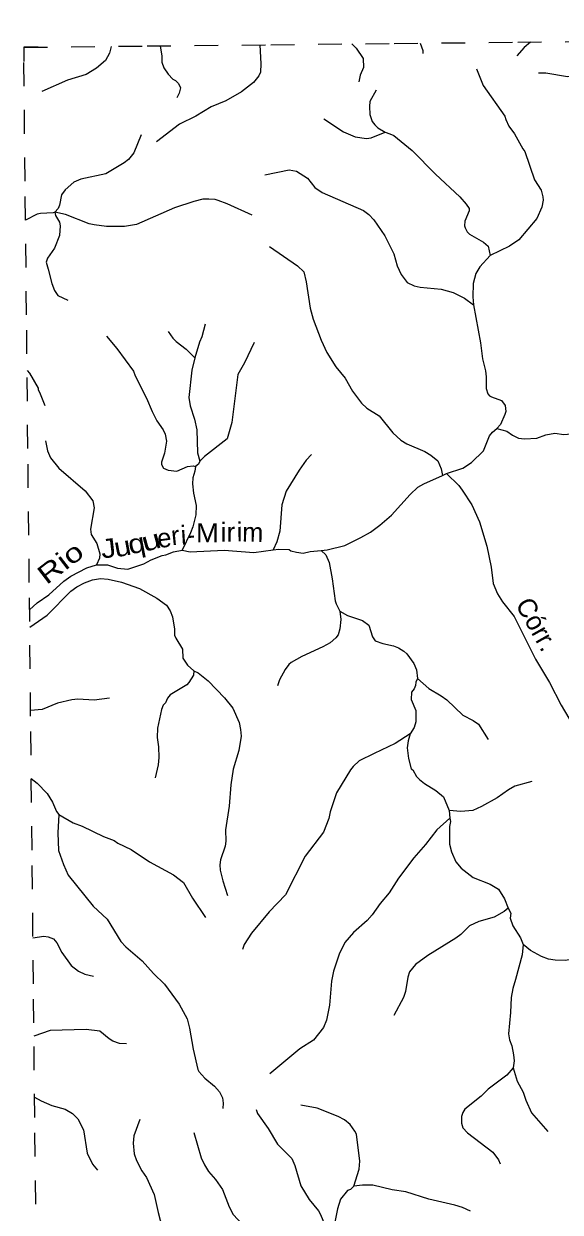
# Model space of a CAD drawing. Extents: x 346.5 to 372.4, y 7400.3 to 7428.2.
# Drawn here: x 346.55 to 348.82, y 7423.08 to 7428.1 of the extents above; entities that cross this region are included whole.
import ezdxf
from ezdxf.enums import TextEntityAlignment as Align

# ---------------------------------------------------------------- set-up
doc = ezdxf.new("R2010")
doc.units = 0
doc.header["$LTSCALE"] = 0.032
doc.linetypes.add('SHORT_DASHED', pattern=[2.7, 1.5, -1.2])
for name, color, linetype, lineweight in [('53', 7, 'SHORT_DASHED', 13), ('63', 7, 'Continuous', 25), ('7', 7, 'Continuous', 25)]:
    doc.layers.add(name, color=color, linetype=linetype, lineweight=lineweight)
doc.layers.add('61', color=7, linetype='Continuous')

msp = doc.modelspace()

# ---------------------------------------------------------------- linework, layer by layer
at = {"layer": '53'}
for points in [[(346.5495, 7428.0029), (347.0715, 7428.0083), (347.5936, 7428.0137), (348.1156, 7428.019), (348.6376, 7428.0243), (349.1596, 7428.0297), (349.6816, 7428.035), (350.2036, 7428.0402), (350.7257, 7428.0455), (351.2477, 7428.0507), (351.7697, 7428.0559), (352.2917, 7428.0611), (352.8137, 7428.0663), (353.3357, 7428.0715), (353.8577, 7428.0766), (354.3798, 7428.0818), (354.9018, 7428.0869), (355.4238, 7428.092), (355.9458, 7428.0971), (356.4678, 7428.1021)], [(346.6314, 7420.0936), (346.6255, 7420.6585), (346.6197, 7421.2235), (346.6138, 7421.7885), (346.608, 7422.3534), (346.6021, 7422.9184), (346.5963, 7423.4833), (346.5904, 7424.0483), (346.5846, 7424.6132), (346.5787, 7425.1782), (346.5729, 7425.7431), (346.567, 7426.3081), (346.5612, 7426.873), (346.5553, 7427.438), (346.5495, 7428.0029)]]:
    msp.add_lwpolyline(points, dxfattribs=at)
at = {"layer": '63'}
msp.add_lwpolyline([(346.6111, 7428.0029), (346.5495, 7428.0029), (346.5495, 7427.9422)], dxfattribs=at)
at = {"layer": '7'}
for points in [[(346.919, 7428.0067), (346.9124, 7427.9785), (346.8956, 7427.9466), (346.8574, 7427.9147), (346.8136, 7427.8885), (346.7347, 7427.8645), (346.6255, 7427.8167)], [(347.548, 7428.0132), (347.5523, 7427.9323), (347.5507, 7427.898), (347.5435, 7427.8829), (347.5204, 7427.8542), (347.4694, 7427.8151), (347.4041, 7427.7761), (347.3411, 7427.7514), (347.2766, 7427.7115), (347.208, 7427.6781), (347.11, 7427.6032)], [(347.1258, 7428.0089), (347.1331, 7427.9658), (347.1331, 7427.9403), (347.1419, 7427.9164), (347.1602, 7427.8893), (347.1801, 7427.8685), (347.1913, 7427.863), (347.2041, 7427.8502), (347.212, 7427.8319), (347.2064, 7427.8096), (347.1961, 7427.7896)], [(347.9368, 7428.0172), (347.9548, 7427.9992), (347.9842, 7427.9554), (347.9858, 7427.9172), (347.9715, 7427.8853), (347.9659, 7427.8566)], [(348.2254, 7428.0201), (348.2361, 7427.9889), (348.2361, 7427.9761)], [(348.6916, 7428.0248), (348.6648, 7428.0024), (348.6338, 7427.9666)], [(348.4632, 7427.9124), (348.4919, 7427.8415), (348.5836, 7427.7123), (348.5867, 7427.698), (348.6003, 7427.6693), (348.6234, 7427.6374), (348.6593, 7427.5737), (348.668, 7427.5633), (348.7087, 7427.443), (348.7358, 7427.3999), (348.7437, 7427.3713), (348.7445, 7427.3569), (348.7398, 7427.3282), (348.7182, 7427.2804), (348.6425, 7427.1903), (348.6027, 7427.1624), (348.5214, 7427.1235)], [(349.2997, 7427.832), (349.2642, 7427.8446), (349.2355, 7427.859), (349.1622, 7427.9044), (349.1303, 7427.9179), (349.1143, 7427.9211), (349.0681, 7427.9243), (349.0251, 7427.9203), (348.9964, 7427.9108), (348.9534, 7427.8901), (348.88, 7427.8789), (348.8482, 7427.8781), (348.7557, 7427.8932), (348.7246, 7427.8941)], [(348.0393, 7427.8215), (348.0129, 7427.7745), (348.0106, 7427.7522), (348.0129, 7427.7187), (348.0225, 7427.69), (348.0337, 7427.6757), (348.0464, 7427.6629), (348.0773, 7427.645)], [(347.8177, 7427.7004), (347.9006, 7427.6462), (347.9508, 7427.6247), (347.9986, 7427.6183), (348.0177, 7427.6207), (348.0773, 7427.645)], [(348.0773, 7427.645), (348.0974, 7427.638), (348.1139, 7427.6308), (348.1915, 7427.5665), (348.2895, 7427.4677), (348.3923, 7427.3712), (348.4194, 7427.341), (348.4321, 7427.3226), (348.4321, 7427.3123), (348.4138, 7427.2692), (348.4122, 7427.2485), (348.4146, 7427.2406), (348.4234, 7427.2238), (348.4337, 7427.2142), (348.4927, 7427.1792), (348.5118, 7427.1632), (348.5214, 7427.1235)], [(347.0463, 7427.6334), (347.0144, 7427.5577), (346.9929, 7427.529), (346.9745, 7427.5147), (346.8964, 7427.4685), (346.7904, 7427.4461), (346.7617, 7427.4334), (346.7251, 7427.4007), (346.7091, 7427.3792), (346.7012, 7427.3362), (346.6948, 7427.3218), (346.6816, 7427.3068)], [(347.5691, 7427.4645), (347.6719, 7427.486), (347.7029, 7427.4796), (347.7484, 7427.4501), (347.7802, 7427.4103), (347.8105, 7427.3896), (347.9859, 7427.3131), (348.0082, 7427.2963), (348.0297, 7427.2748), (348.0751, 7427.2071), (348.1134, 7427.1306), (348.1285, 7427.0796), (348.1444, 7427.0429), (348.17, 7427.0102), (348.1994, 7426.9959), (348.2249, 7426.9895), (348.3142, 7426.9815), (348.3652, 7426.968), (348.413, 7426.9433), (348.4507, 7426.9158)], [(347.5149, 7427.2939), (347.4089, 7427.3418), (347.3706, 7427.3561), (347.3579, 7427.3601), (347.3324, 7427.3617), (347.3069, 7427.3609), (347.2686, 7427.3521), (347.1873, 7427.3242), (347.0263, 7427.2549), (346.9753, 7427.2461), (346.8988, 7427.2461), (346.8478, 7427.2525), (346.8255, 7427.2573), (346.7259, 7427.2971), (346.6816, 7427.3068)], [(346.6816, 7427.3068), (346.6741, 7427.3033), (346.6199, 7427.3011), (346.6056, 7427.2979), (346.557, 7427.2731)], [(346.6816, 7427.3068), (346.6836, 7427.293), (346.7004, 7427.2645), (346.7028, 7427.2485), (346.7012, 7427.2079), (346.6789, 7427.1545), (346.6506, 7427.1117), (346.6445, 7427.0948), (346.6526, 7427.0652), (346.6677, 7427.0047), (346.6797, 7426.976), (346.6932, 7426.9552), (346.7355, 7426.9345)], [(347.5882, 7427.1617), (347.7061, 7427.0804), (347.7332, 7427.0549), (347.7436, 7427.0126), (347.7595, 7426.9011), (347.7731, 7426.8548), (347.8065, 7426.7656), (347.8312, 7426.7146), (347.8687, 7426.654), (347.9077, 7426.6062), (347.9388, 7426.5504), (347.9771, 7426.4994), (347.9994, 7426.4787), (348.052, 7426.4468), (348.1102, 7426.3743), (348.1436, 7426.3432), (348.1692, 7426.328), (348.2441, 7426.2962), (348.2696, 7426.281), (348.2998, 7426.2563), (348.3062, 7426.2396), (348.3134, 7426.2221), (348.3193, 7426.1943)], [(348.5214, 7427.1235), (348.4768, 7427.0764), (348.4608, 7427.0477), (348.4497, 7427.0047), (348.4473, 7426.9497), (348.4507, 7426.9158)], [(348.4507, 7426.9158), (348.4807, 7426.7544), (348.4879, 7426.6875), (348.5007, 7426.6365), (348.5039, 7426.611), (348.5039, 7426.5616), (348.511, 7426.54), (348.5182, 7426.5313), (348.5262, 7426.5273), (348.5692, 7426.5113), (348.5844, 7426.4898), (348.5867, 7426.4643), (348.5836, 7426.4516), (348.5641, 7426.4093), (348.5493, 7426.3934)], [(347.3164, 7426.8333), (347.3021, 7426.7799), (347.2925, 7426.7576), (347.2729, 7426.6918)], [(346.8996, 7426.7823), (346.9426, 7426.7305), (347.0136, 7426.6349), (347.0199, 7426.6157), (347.0678, 7426.5217), (347.0925, 7426.4643), (347.1124, 7426.4261), (347.1387, 7426.3878), (347.1467, 7426.3687), (347.1522, 7426.34), (347.1443, 7426.289), (347.1323, 7426.2507), (347.1323, 7426.2404), (347.1395, 7426.226), (347.1594, 7426.2165), (347.1961, 7426.2125), (347.2415, 7426.2332), (347.2656, 7426.235), (347.275, 7426.2326)], [(347.1594, 7426.803), (347.1801, 7426.7743), (347.1937, 7426.7608), (347.2367, 7426.7281), (347.2729, 7426.6918)], [(347.5236, 7426.7568), (347.4822, 7426.6699), (347.4543, 7426.6205), (347.4296, 7426.4181), (347.4089, 7426.3488), (347.3132, 7426.2754), (347.2933, 7426.2551)], [(347.2729, 7426.6918), (347.2606, 7426.6397), (347.2479, 7426.5233), (347.2527, 7426.4882), (347.271, 7426.4325), (347.2805, 7426.3878), (347.2845, 7426.2906), (347.2933, 7426.2551)], [(346.5636, 7426.6378), (346.5744, 7426.6269), (346.6103, 7426.5639), (346.6103, 7426.5576), (346.6191, 7426.5401), (346.6385, 7426.49)], [(348.3369, 7426.2025), (348.4051, 7426.2252), (348.4417, 7426.2499), (348.4927, 7426.2994), (348.5182, 7426.3623), (348.5302, 7426.3775), (348.5493, 7426.3934)], [(348.5493, 7426.3934), (348.5915, 7426.3822), (348.6154, 7426.3655), (348.641, 7426.3527), (348.6665, 7426.3496), (348.7175, 7426.3527), (348.7557, 7426.3663), (348.794, 7426.3735), (348.8322, 7426.3671), (348.8936, 7426.3735), (348.9119, 7426.3615), (348.9191, 7426.3424), (348.9271, 7426.3376), (348.9461, 7426.3404), (348.9543, 7426.3487)], [(346.6412, 7426.3404), (346.6494, 7426.2986), (346.6629, 7426.2699), (346.6972, 7426.2252), (346.8088, 7426.1296), (346.8422, 7426.0874), (346.847, 7426.0579), (346.8311, 7425.9686), (346.8343, 7425.9455), (346.8582, 7425.9081), (346.8706, 7425.8639), (346.8694, 7425.8451), (346.8577, 7425.818)], [(347.7659, 7426.2834), (347.7436, 7426.2587), (347.7133, 7426.2173), (347.6583, 7426.1288), (347.6408, 7426.0706), (347.632, 7425.9591), (347.6192, 7425.9144), (347.6039, 7425.8811)], [(347.275, 7426.2326), (347.2727, 7426.213), (347.2638, 7426.1854), (347.2622, 7426.1599), (347.267, 7426.12), (347.2782, 7426.0675), (347.2766, 7426.0292), (347.2638, 7425.9782), (347.2542, 7425.9527), (347.2195, 7425.8787)], [(347.2933, 7426.2551), (347.2878, 7426.2427), (347.275, 7426.2326)], [(347.8065, 7425.8778), (347.8324, 7425.8813), (347.9062, 7425.8993), (347.9747, 7425.9327), (348.0153, 7425.9559), (348.0544, 7425.9845), (348.1038, 7426.0268), (348.1835, 7426.1145), (348.2154, 7426.1447), (348.2409, 7426.1591), (348.3193, 7426.1943), (348.3369, 7426.2025)], [(348.3369, 7426.2025), (348.3883, 7426.1527), (348.4026, 7426.132), (348.4433, 7426.0706), (348.476, 7425.9989), (348.5063, 7425.8969), (348.5246, 7425.8076), (348.5333, 7425.7391), (348.5525, 7425.6945), (348.5724, 7425.661), (348.6226, 7425.5996), (348.7127, 7425.4187), (348.7716, 7425.3207), (348.821, 7425.2243), (348.8529, 7425.1701), (348.8816, 7425.131), (348.9478, 7425.0561), (348.9924, 7425.0059), (349.0314, 7424.9477)], [(346.8577, 7425.818), (346.9036, 7425.818), (346.9451, 7425.8036), (346.9897, 7425.7997), (347.0566, 7425.822), (347.0877, 7425.8387), (347.1347, 7425.8562), (347.1507, 7425.8594), (347.1825, 7425.8722), (347.2195, 7425.8787)], [(347.2195, 7425.8787), (347.2536, 7425.8716), (347.3961, 7425.8794), (347.522, 7425.8698), (347.6039, 7425.8811)], [(347.6039, 7425.8811), (347.6274, 7425.8835), (347.6715, 7425.8817), (347.6782, 7425.877), (347.7021, 7425.8706), (347.7308, 7425.8666), (347.7595, 7425.873), (347.8065, 7425.8778)], [(347.8065, 7425.8778), (347.8258, 7425.8597), (347.8403, 7425.8273), (347.8536, 7425.7582), (347.8663, 7425.6658), (347.8695, 7425.653), (347.8849, 7425.6218)], [(346.5741, 7425.628), (346.6056, 7425.657), (346.6549, 7425.6913), (346.7187, 7425.7487), (346.7482, 7425.7702), (346.8159, 7425.8052), (346.8577, 7425.818)], [(346.5748, 7425.5541), (346.6478, 7425.6044), (346.7482, 7425.7056), (346.7745, 7425.7247), (346.8064, 7425.7415), (346.8399, 7425.7542), (346.8733, 7425.7598), (346.9068, 7425.7566), (346.9626, 7425.7447), (347.0391, 7425.7168), (347.1124, 7425.6761), (347.153, 7425.6467), (347.1682, 7425.6228), (347.1777, 7425.5973), (347.1865, 7425.5462), (347.1873, 7425.5207), (347.1921, 7425.508), (347.2208, 7425.461), (347.2224, 7425.4235), (347.2423, 7425.3932), (347.2682, 7425.3699)], [(347.8849, 7425.6218), (347.8902, 7425.5861), (347.8862, 7425.5478), (347.8783, 7425.5223), (347.8687, 7425.5088), (347.844, 7425.4881), (347.8137, 7425.4705), (347.7245, 7425.4307), (347.6798, 7425.4052), (347.6703, 7425.3972), (347.6551, 7425.3757), (347.6312, 7425.3311), (347.6217, 7425.3064)], [(347.8849, 7425.6218), (347.9173, 7425.6028), (347.9811, 7425.5821), (348.0074, 7425.563), (348.0241, 7425.5128), (348.0353, 7425.4968), (348.0671, 7425.4849), (348.1118, 7425.4753), (348.1341, 7425.4673), (348.1556, 7425.4522), (348.1683, 7425.441), (348.1986, 7425.4012), (348.209, 7425.3741), (348.2144, 7425.3378)], [(347.2682, 7425.3699), (347.2667, 7425.3511), (347.2479, 7425.3207), (347.2383, 7425.3111), (347.1682, 7425.2681), (347.157, 7425.2546), (347.1483, 7425.2346), (347.1387, 7425.2243), (347.1315, 7425.2067), (347.1148, 7425.1271), (347.114, 7425.0888), (347.1196, 7425.049), (347.1204, 7425.0043), (347.1172, 7424.9724), (347.1044, 7424.9175)], [(347.2682, 7425.3699), (347.2861, 7425.3609), (347.3284, 7425.3271), (347.3977, 7425.2554), (347.4336, 7425.2115), (347.4599, 7425.151), (347.4662, 7425.1223), (347.4678, 7425.0936), (347.4583, 7425.033), (347.4344, 7424.9549), (347.4248, 7424.888), (347.4176, 7424.7987), (347.4025, 7424.6983), (347.4041, 7424.6505), (347.4005, 7424.6288), (347.381, 7424.5724), (347.3786, 7424.5501), (347.3802, 7424.5278), (347.3913, 7424.4831), (347.4105, 7424.4218)], [(348.2144, 7425.3378), (348.2062, 7425.3219), (348.205, 7425.3072), (348.1994, 7425.2944), (348.1883, 7425.2801), (348.1867, 7425.249), (348.2066, 7425.2028), (348.2066, 7425.1542), (348.1994, 7425.131), (348.1821, 7425.1043)], [(348.2144, 7425.3378), (348.2612, 7425.2952), (348.3142, 7425.2649), (348.3381, 7425.2474), (348.4058, 7425.1828), (348.4497, 7425.1605), (348.472, 7425.1446), (348.5118, 7425.08)], [(346.9124, 7425.2546), (346.8478, 7425.2458), (346.7777, 7425.2498), (346.7522, 7425.2474), (346.6916, 7425.233), (346.6279, 7425.2059), (346.5785, 7425.2021)], [(348.1821, 7425.1043), (348.1197, 7425.0633), (348.0305, 7425.021), (347.9667, 7424.99), (347.9412, 7424.9661), (347.9309, 7424.9517), (347.8711, 7424.8545), (347.8448, 7424.7748), (347.8384, 7424.7461), (347.8169, 7424.6887), (347.7388, 7424.5867), (347.6559, 7424.4241), (347.5866, 7424.3516), (347.5125, 7424.2616), (347.4814, 7424.2138), (347.4742, 7424.1938)], [(348.1821, 7425.1043), (348.1739, 7425.0745), (348.1707, 7425.0442), (348.1755, 7424.9995), (348.1875, 7424.9565), (348.1939, 7424.9517), (348.2098, 7424.923), (348.2225, 7424.9103), (348.2433, 7424.8935), (348.2919, 7424.864), (348.3238, 7424.8377), (348.348, 7424.7798), (348.3501, 7424.7481)], [(346.5815, 7424.9158), (346.6063, 7424.8959), (346.6486, 7424.8513), (346.6717, 7424.8147), (346.6878, 7424.7755), (346.6974, 7424.7631)], [(348.6975, 7424.9023), (348.625, 7424.8824), (348.5987, 7424.868), (348.5501, 7424.8338), (348.4847, 7424.7971), (348.4481, 7424.7804), (348.3971, 7424.7764), (348.348, 7424.7798)], [(346.6974, 7424.7631), (346.6932, 7424.6855), (346.6964, 7424.6106), (346.7171, 7424.5517), (346.737, 7424.507), (346.843, 7424.3755), (346.9028, 7424.3205), (346.9594, 7424.2273), (346.9817, 7424.2042), (347.0502, 7424.1452), (347.098, 7424.0918), (347.1443, 7424.0464), (347.2064, 7423.9619), (347.2407, 7423.8998), (347.2503, 7423.8615), (347.2654, 7423.7722), (347.2853, 7423.6862), (347.2901, 7423.6774), (347.3156, 7423.6503), (347.3563, 7423.616), (347.377, 7423.5921), (347.3897, 7423.5666), (347.3929, 7423.5443), (347.3905, 7423.5212)], [(346.6974, 7424.7631), (346.7586, 7424.7278), (346.7968, 7424.7134), (346.8861, 7424.6704), (346.9323, 7424.6528), (346.9474, 7424.6417), (347.004, 7424.6154), (347.0805, 7424.5628), (347.1825, 7424.5086), (347.2248, 7424.4759), (347.2622, 7424.4098), (347.3172, 7424.3277)], [(348.3501, 7424.7481), (348.2951, 7424.6991), (348.248, 7424.6361), (348.1978, 7424.5803), (348.1341, 7424.4943), (348.0934, 7424.4329), (348.056, 7424.3875), (348.0217, 7424.3389), (348.001, 7424.315), (347.9436, 7424.2647), (347.9062, 7424.2225), (347.883, 7424.1739), (347.8583, 7424.1022), (347.8496, 7424.0591), (347.8416, 7423.9587), (347.8296, 7423.895), (347.8169, 7423.8631), (347.7739, 7423.8097), (347.7165, 7423.7738), (347.5898, 7423.6678)], [(348.3501, 7424.7481), (348.3528, 7424.7336), (348.3491, 7424.7127), (348.3493, 7424.6377), (348.3572, 7424.6059), (348.3763, 7424.5628), (348.3987, 7424.5365), (348.4497, 7424.4967), (348.5214, 7424.4696), (348.5557, 7424.4472), (348.5812, 7424.4066), (348.597, 7424.367)], [(348.597, 7424.367), (348.5804, 7424.3532), (348.5373, 7424.3301), (348.4736, 7424.3118), (348.4337, 7424.2934), (348.3971, 7424.2568), (348.3764, 7424.2416), (348.2568, 7424.1683), (348.2058, 7424.1293), (348.1795, 7424.099), (348.1723, 7424.0767), (348.1628, 7424.0161), (348.1548, 7423.9906), (348.1142, 7423.9149)], [(348.597, 7424.367), (348.608, 7424.3463), (348.6059, 7424.3261), (348.617, 7424.2934), (348.6489, 7424.2424), (348.6611, 7424.2141)], [(346.5884, 7424.2419), (346.6342, 7424.2488), (346.6534, 7424.2464), (346.6757, 7424.2385), (346.6892, 7424.2217), (346.7099, 7424.1811), (346.7506, 7424.1261), (346.7816, 7424.1014), (346.808, 7424.0894), (346.8438, 7424.0799)], [(349.1853, 7424.2448), (349.1287, 7424.2329), (349.0219, 7424.2217), (349.0075, 7424.2177), (348.9796, 7424.2074), (348.9263, 7424.1747), (348.8976, 7424.1611), (348.8705, 7424.1516), (348.8386, 7424.146), (348.7956, 7424.1476), (348.7669, 7424.1524), (348.7382, 7424.1635), (348.692, 7424.1882), (348.6611, 7424.2141)], [(348.6611, 7424.2141), (348.6566, 7424.1711), (348.6282, 7424.0671), (348.6162, 7424.0289), (348.6099, 7423.9906), (348.6075, 7423.9269), (348.5987, 7423.8376), (348.6027, 7423.8121), (348.613, 7423.7866), (348.6202, 7423.7483), (348.6218, 7423.7228), (348.6181, 7423.693)], [(346.9841, 7423.7946), (346.9546, 7423.7961), (346.9259, 7423.8065), (346.91, 7423.8161), (346.8717, 7423.8487), (346.8128, 7423.8551), (346.6613, 7423.8511), (346.5927, 7423.8266)], [(348.6181, 7423.693), (348.5907, 7423.6631), (348.5126, 7423.6033), (348.4831, 7423.5738), (348.4138, 7423.5188), (348.405, 7423.5053), (348.4003, 7423.4877), (348.4003, 7423.4598), (348.4058, 7423.4399), (348.4258, 7423.4184), (348.5326, 7423.3371), (348.5565, 7423.3052), (348.5636, 7423.2885)], [(348.6181, 7423.693), (348.6346, 7423.6376), (348.6609, 7423.5905), (348.6712, 7423.5571), (348.6959, 7423.5029), (348.7645, 7423.424)], [(346.5954, 7423.569), (346.6231, 7423.5547), (346.6677, 7423.5339), (346.7243, 7423.5196), (346.7562, 7423.5005), (346.7777, 7423.4782), (346.8016, 7423.4312), (346.8175, 7423.3331), (346.8406, 7423.2869), (346.8614, 7423.2614)], [(347.9444, 7423.1931), (347.9667, 7423.2654), (347.9699, 7423.2989), (347.9564, 7423.4136), (347.9492, 7423.4264), (347.9285, 7423.4535), (347.9046, 7423.4734), (347.8791, 7423.4885), (347.7898, 7423.5236), (347.7205, 7423.5364)], [(347.0399, 7423.475), (347.0152, 7423.4057), (347.012, 7423.3754), (347.0168, 7423.3307), (347.0263, 7423.302), (347.0486, 7423.259), (347.0678, 7423.2303), (347.1004, 7423.1586), (347.1172, 7423.0821), (347.1267, 7423.0502), (347.1411, 7423.0183), (347.1602, 7422.9865), (347.2016, 7422.9386), (347.2335, 7422.9131), (347.2622, 7422.8844), (347.31, 7422.847), (347.3794, 7422.8023), (347.4474, 7422.7514)], [(347.5316, 7423.518), (347.538, 7423.5013), (347.5826, 7423.4375), (347.6216, 7423.3714), (347.6822, 7423.31), (347.6958, 7423.2813), (347.7205, 7423.1953), (347.7555, 7423.1379), (347.7954, 7423.0901), (347.8041, 7423.0741), (347.8201, 7423.0335), (347.8254, 7423.0065), (347.8232, 7422.982)], [(347.2678, 7423.4208), (347.2997, 7423.3132), (347.3132, 7423.2845), (347.3308, 7423.2558), (347.3594, 7423.2224), (347.3889, 7423.1793), (347.4184, 7423.106), (347.4352, 7423.0741), (347.4726, 7423.0335), (347.479, 7423.0175), (347.4822, 7423.0159), (347.4885, 7422.9801), (347.4854, 7422.9339), (347.4503, 7422.8191), (347.4474, 7422.7514)], [(347.9444, 7423.1931), (347.931, 7423.1802), (347.9179, 7423.1754), (347.8878, 7423.1387), (347.8751, 7423.098), (347.8623, 7423.0343), (347.8502, 7423.0037)], [(348.4377, 7423.0877), (348.4035, 7423.1036), (348.3716, 7423.114), (348.2616, 7423.1395), (348.1644, 7423.1705), (348.107, 7423.1785), (348.0257, 7423.1976), (347.9811, 7423.1984), (347.9444, 7423.1931)]]:
    msp.add_lwpolyline(points, dxfattribs=at)

# ---------------------------------------------------------------- texts
at = {"layer": '61'}
for s, rotation, p in [('i', 3.521, (347.227, 7425.9033)), ('i', 0.841, (347.4622, 7425.9164)), ('m', 358.635, (347.5167, 7425.9151)), ('e', 7.599, (347.1484, 7425.8917)), ('r', 6.023, (347.1939, 7425.902)), ('Córr.', 299.358, (348.6838, 7425.5468))]:
    msp.add_text(s, height=0.08, rotation=rotation, dxfattribs=at).set_placement(p, align=Align.CENTER)
at = {"layer": '61', "width": 1.1}
msp.add_text('M', height=0.08, dxfattribs=at).set_placement((347.3261, 7425.9125), align=Align.CENTER)
at = {"layer": '61'}
for s, p in [('i', (347.3938, 7425.9159)), ('r', (347.4253, 7425.9159))]:
    msp.add_text(s, height=0.08, dxfattribs=at).set_placement(p, align=Align.CENTER)
for s, rotation, width, p in [('J', 6.795, 1.2, (346.9119, 7425.848)), ('q', 10.827, 1.2, (347.0336, 7425.8683)), ('u', 15.524, 1.35, (347.0981, 7425.8818)), ('-', 3.521, 0.9, (347.259, 7425.9052)), ('Rio', 37.626, 1.3, (346.7286, 7425.7943)), ('u', 10.827, 1.2, (346.9739, 7425.8552))]:
    msp.add_text(s, height=0.08, rotation=rotation, dxfattribs=dict(at, width=width)).set_placement(p, align=Align.CENTER)

doc.saveas('drawing.dxf')
